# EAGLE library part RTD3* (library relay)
Power PCB Relay SCHRACK 1 pole 12 / 16 A, DC- or AC-coil Source: http://www.schrack.com/.. 5819.pdf
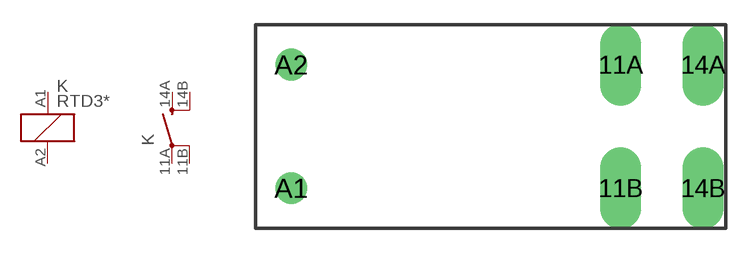
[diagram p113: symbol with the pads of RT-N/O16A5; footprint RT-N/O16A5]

Designator prefix K; gates 1=K 2=S-X2

## RTD34005 (MF: TYCO ELECTRONICS; MPN: RTD34005; OC_FARNELL: unknown; OC_NEWARK: 93B4654), RTD34006 (OC_FARNELL: unknown; OC_NEWARK: unknown), RTD34012 (MF: TYCO ELECTRONICS; MPN: RTD34012F; OC_FARNELL: unknown; OC_NEWARK: 36K3470), RTD34024 (MF: TYCO ELECTRONICS; MPN: RTD34024F; OC_FARNELL: 9850961; OC_NEWARK: 34K0187), RTD34048 (MF: TYCO ELECTRONICS; MPN: RTD34048; OC_FARNELL: unknown; OC_NEWARK: 08H3709), RTD34060 (OC_FARNELL: unknown; OC_NEWARK: unknown), RTD34110 (OC_FARNELL: unknown; OC_NEWARK: unknown), RTD34524 (OC_FARNELL: unknown; OC_NEWARK: unknown), RTD34615 (MF: TYCO ELECTRONICS; MPN: RTD34615; OC_FARNELL: unknown; OC_NEWARK: 48F1293), RTD34730 (MF: TYCO ELECTRONICS; MPN: RTD34730; OC_FARNELL: unknown; OC_NEWARK: 85C1167)  [RT-N/O16A5]
11A  2:PA  pas
11B  2:PB  pas
14A  2:SA  pas
14B  2:SB  pas
A1  1:1  pas
A2  1:2  pas

## Footprint RT-N/O16A5 (pad centres in mm)
Power PCB Relay 1 pole 12 / 16 A, DC- or AC-coil SCHRACK 16 A, pinning 5mm Source: http://www.schrack.com/.. 5819.pdf
drill 1.3 pad 2.5 long: 11A 7.56,3.78; 11B 7.56,-3.78; 14A 12.6,3.78; 14B 12.6,-3.78
drill 1.3 round: A1 -12.6,-3.78; A2 -12.6,3.78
